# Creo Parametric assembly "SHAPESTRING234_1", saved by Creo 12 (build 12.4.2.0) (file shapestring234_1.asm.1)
Units: Custom; MM, KILOGRAM, SECS

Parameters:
  PTC_WM_ITERATION = "0"
  PTC_WM_VERSION = "-.0"
  PTC_WM_LIFECYCLE_STATE = "In Work"
  PTC_WM_LIFECYCLE = "MO_CADDocument"
  PTC_WM_CREATED_BY = "Maximilian Roepper (Z0017RMS: MO)"
  PTC_WM_CREATED_ON = "18-Sep-26 11:36:42 AM"
  PTC_WM_MODIFIED_BY = "Maximilian Roepper (Z0017RMS: MO)"
  PTC_WM_MODIFIED_ON = "18-Sep-26 11:36:46 AM"
  PDMLINKNUMBER = "PDM000071455178"
  PTC_WM_NAME = "shapestring234_1.asm"
  PTC_WM_NUMBER = "PDM000071455178"

Other parameters: WEIGHT, WEIGHT_FACTOR, WEIGHT_ADD, MC_ERRORS, SUPPLIER, ISPOSITIONINGASSEMBLY

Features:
  1. coordinate system
  2. imported feature
  3. component "SHAPESTRING092_1"
  4. component "SHAPESTRING233_1"

Other named items: DRW_VIEW_ORG, ROUGH-GROB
